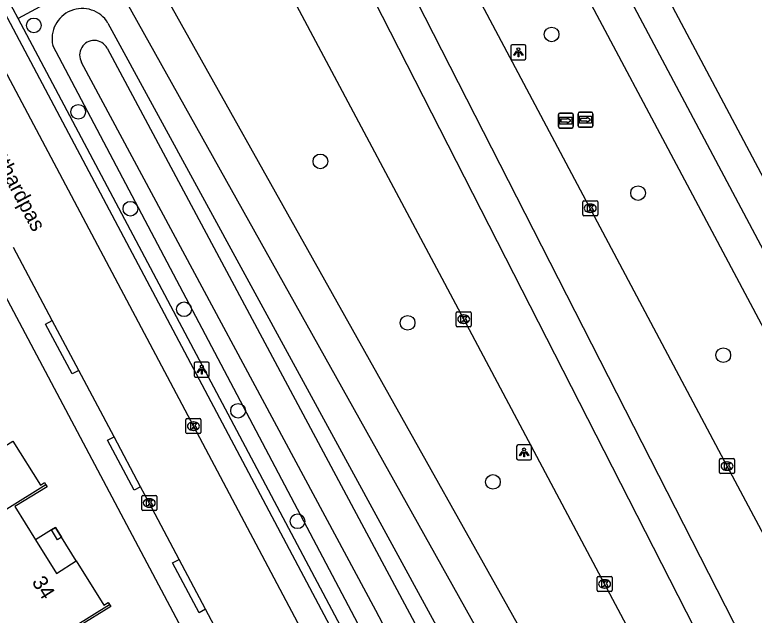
# Model space of a CAD drawing. Extents: x 158838 to 160074, y 386376 to 387776.
# Drawn here: x 159225.91 to 159275.17, y 387072.03 to 387112.04 of the extents above; entities that cross this region are included whole.
import ezdxf

# ---------------------------------------------------------------- set-up
doc = ezdxf.new("R2010")
doc.units = 0
for name, color, linetype in [('IMGEO_Berm_groen', 7, 'Continuous'), ('IMGEO_Boom', 7, 'Continuous'), ('IMGEO_Fietspad_gesloten', 7, 'Continuous'), ('IMGEO_Kolk', 7, 'Continuous'), ('IMGEO_Lichtpunt', 7, 'Continuous'), ('IMGEO_Openbare_ruimte_label', 7, 'Continuous'), ('IMGEO_Pand', 7, 'Continuous'), ('IMGEO_Pand_nummerreeks', 7, 'Continuous'), ('IMGEO_Pand_overbouw', 7, 'Continuous'), ('IMGEO_Rijbaan_lokaal_gesloten', 7, 'Continuous'), ('IMGEO_Rijbaan_lokaal_open', 7, 'Continuous'), ('IMGEO_Voetpad_open', 7, 'Continuous'), ('IMGEO_Waterloop', 7, 'Continuous'), ('IMGEO_Wegwijzer', 7, 'Continuous')]:
    doc.layers.add(name, color=color, linetype=linetype)

msp = doc.modelspace()

# ---------------------------------------------------------------- linework, layer by layer
at = {"layer": 'IMGEO_Berm_groen'}
for points in [[(159232.122, 387111.496), (159272.514, 387037.369)], [(159268.044, 387034.942), (159228.447, 387109.997)]]:
    msp.add_lwpolyline(points, dxfattribs=at)
msp.add_arc((159230.405, 387110.451), 2.01, 31.3221, 193.0582, dxfattribs=at)
at = {"layer": 'IMGEO_Boom'}
for centre in [(159227.183, 387111.339), (159261.673, 387110.732), (159230.14, 387105.578), (159246.274, 387102.278), (159267.435, 387100.161), (159233.613, 387099.119), (159237.187, 387092.418), (159252.081, 387091.516), (159273.111, 387089.363), (159240.785, 387085.656), (159257.766, 387080.919), (159244.747, 387078.294)]:
    msp.add_circle(centre, 0.489, dxfattribs=at)
at = {"layer": 'IMGEO_Fietspad_gesloten'}
for points in [[(159314.185, 387024.122), (159313.935, 387024.592), (159304.248, 387042.785), (159259.512, 387127.003), (159257.832, 387130.098)], [(159256.446, 387127.537), (159257.729, 387125.109), (159294.989, 387055.058)], [(159234.539, 387115.845), (159274.567, 387044.384)], [(159272.288, 387043.244), (159232.161, 387115.069)]]:
    msp.add_lwpolyline(points, dxfattribs=at)
at = {"layer": 'IMGEO_Kolk'}
for p, q in [((159263.745, 387098.725), (159263.745, 387099.577)), ((159263.82, 387099.651), (159264.672, 387099.651)), ((159264.746, 387099.577), (159264.746, 387098.725)), ((159264.233, 387099.431), (159264.258, 387099.431)), ((159264.672, 387098.651), (159263.82, 387098.651)), ((159264.256, 387098.871), (159264.231, 387098.871)), ((159255.318, 387091.334), (159255.318, 387092.186)), ((159255.393, 387092.26), (159256.245, 387092.26)), ((159256.319, 387092.186), (159256.319, 387091.334)), ((159255.806, 387092.04), (159255.831, 387092.04)), ((159256.245, 387091.26), (159255.393, 387091.26)), ((159255.829, 387091.48), (159255.804, 387091.48)), ((159237.315, 387084.207), (159237.315, 387085.059)), ((159237.39, 387085.133), (159238.242, 387085.133)), ((159237.803, 387084.913), (159237.828, 387084.913)), ((159238.316, 387085.059), (159238.316, 387084.207)), ((159237.826, 387084.353), (159237.801, 387084.353)), ((159238.242, 387084.133), (159237.39, 387084.133)), ((159272.862, 387081.547), (159272.862, 387082.399)), ((159272.937, 387082.473), (159273.789, 387082.473)), ((159273.35, 387082.253), (159273.375, 387082.253)), ((159273.863, 387082.399), (159273.863, 387081.547)), ((159273.789, 387081.473), (159272.937, 387081.473)), ((159273.373, 387081.693), (159273.348, 387081.693)), ((159234.374, 387079.086), (159234.374, 387079.938)), ((159234.449, 387080.012), (159235.301, 387080.012)), ((159234.862, 387079.792), (159234.887, 387079.792)), ((159235.375, 387079.938), (159235.375, 387079.086)), ((159235.301, 387079.012), (159234.449, 387079.012)), ((159234.885, 387079.232), (159234.86, 387079.232)), ((159264.707, 387073.693), (159264.707, 387074.545)), ((159264.782, 387074.619), (159265.634, 387074.619)), ((159265.195, 387074.399), (159265.22, 387074.399)), ((159265.708, 387074.545), (159265.708, 387073.693)), ((159265.634, 387073.619), (159264.782, 387073.619)), ((159265.218, 387073.839), (159265.193, 387073.839))]:
    msp.add_line(p, q, dxfattribs=at)
for points in [[(159263.745, 387098.725), (159263.745, 387099.577)], [(159263.82, 387099.651), (159264.672, 387099.651)], [(159264.746, 387099.577), (159264.746, 387098.725)], [(159264.066, 387099.351), (159264.189, 387099.351), (159264.189, 387099.2), (159264.319, 387099.351), (159264.483, 387099.351), (159264.337, 387099.2), (159264.49, 387098.951), (159264.338, 387098.951), (159264.253, 387099.115), (159264.189, 387099.048), (159264.189, 387098.951), (159264.066, 387098.951), (159264.066, 387099.351)], [(159264.672, 387098.651), (159263.82, 387098.651)], [(159255.318, 387091.334), (159255.318, 387092.186)], [(159255.393, 387092.26), (159256.245, 387092.26)], [(159256.319, 387092.186), (159256.319, 387091.334)], [(159255.639, 387091.96), (159255.762, 387091.96), (159255.762, 387091.809), (159255.892, 387091.96), (159256.056, 387091.96), (159255.91, 387091.809), (159256.063, 387091.56), (159255.911, 387091.56), (159255.826, 387091.724), (159255.762, 387091.657), (159255.762, 387091.56), (159255.639, 387091.56), (159255.639, 387091.96)], [(159256.245, 387091.26), (159255.393, 387091.26)], [(159237.315, 387084.207), (159237.315, 387085.059)], [(159237.39, 387085.133), (159238.242, 387085.133)], [(159237.636, 387084.833), (159237.759, 387084.833), (159237.759, 387084.682), (159237.889, 387084.833), (159238.053, 387084.833), (159237.907, 387084.682), (159238.06, 387084.433), (159237.908, 387084.433), (159237.823, 387084.597), (159237.759, 387084.53), (159237.759, 387084.433), (159237.636, 387084.433), (159237.636, 387084.833)], [(159238.316, 387085.059), (159238.316, 387084.207)], [(159238.242, 387084.133), (159237.39, 387084.133)], [(159272.862, 387081.547), (159272.862, 387082.399)], [(159272.937, 387082.473), (159273.789, 387082.473)], [(159273.863, 387082.399), (159273.863, 387081.547)], [(159273.183, 387082.173), (159273.306, 387082.173), (159273.306, 387082.022), (159273.436, 387082.173), (159273.6, 387082.173), (159273.454, 387082.022), (159273.607, 387081.773), (159273.455, 387081.773), (159273.37, 387081.937), (159273.306, 387081.87), (159273.306, 387081.773), (159273.183, 387081.773), (159273.183, 387082.173)], [(159273.789, 387081.473), (159272.937, 387081.473)], [(159234.374, 387079.086), (159234.374, 387079.938)], [(159234.449, 387080.012), (159235.301, 387080.012)], [(159235.375, 387079.938), (159235.375, 387079.086)], [(159234.695, 387079.712), (159234.818, 387079.712), (159234.818, 387079.561), (159234.948, 387079.712), (159235.112, 387079.712), (159234.966, 387079.561), (159235.119, 387079.312), (159234.967, 387079.312), (159234.882, 387079.476), (159234.818, 387079.409), (159234.818, 387079.312), (159234.695, 387079.312), (159234.695, 387079.712)], [(159235.301, 387079.012), (159234.449, 387079.012)], [(159264.707, 387073.693), (159264.707, 387074.545)], [(159264.782, 387074.619), (159265.634, 387074.619)], [(159265.708, 387074.545), (159265.708, 387073.693)], [(159265.028, 387074.319), (159265.151, 387074.319), (159265.151, 387074.168), (159265.281, 387074.319), (159265.445, 387074.319), (159265.299, 387074.168), (159265.452, 387073.919), (159265.3, 387073.919), (159265.215, 387074.083), (159265.151, 387074.016), (159265.151, 387073.919), (159265.028, 387073.919), (159265.028, 387074.319)], [(159265.634, 387073.619), (159264.782, 387073.619)]]:
    msp.add_lwpolyline(points, dxfattribs=at)
for centre, start, end in [((159263.822, 387099.575), 91.552, 178.448), ((159263.822, 387099.575), 91.552, 178.448), ((159264.67, 387099.575), 1.552, 88.448), ((159264.67, 387099.575), 1.552, 88.448), ((159263.822, 387098.727), 181.552, 268.448), ((159263.822, 387098.727), 181.552, 268.448), ((159264.67, 387098.727), 271.552, 358.448), ((159264.67, 387098.727), 271.552, 358.448), ((159255.395, 387092.184), 91.552, 178.448), ((159255.395, 387092.184), 91.552, 178.448), ((159256.243, 387092.184), 1.552, 88.448), ((159256.243, 387092.184), 1.552, 88.448), ((159255.395, 387091.336), 181.552, 268.448), ((159255.395, 387091.336), 181.552, 268.448), ((159256.243, 387091.336), 271.552, 358.448), ((159256.243, 387091.336), 271.552, 358.448), ((159237.392, 387085.057), 91.552, 178.448), ((159237.392, 387085.057), 91.552, 178.448), ((159238.24, 387085.057), 1.552, 88.448), ((159238.24, 387085.057), 1.552, 88.448), ((159237.392, 387084.209), 181.552, 268.448), ((159237.392, 387084.209), 181.552, 268.448), ((159238.24, 387084.209), 271.552, 358.448), ((159238.24, 387084.209), 271.552, 358.448), ((159272.939, 387082.397), 91.552, 178.448), ((159272.939, 387082.397), 91.552, 178.448), ((159273.787, 387082.397), 1.552, 88.448), ((159273.787, 387082.397), 1.552, 88.448), ((159272.939, 387081.549), 181.552, 268.448), ((159272.939, 387081.549), 181.552, 268.448), ((159273.787, 387081.549), 271.552, 358.448), ((159273.787, 387081.549), 271.552, 358.448), ((159234.451, 387079.936), 91.552, 178.448), ((159234.451, 387079.936), 91.552, 178.448), ((159235.299, 387079.936), 1.552, 88.448), ((159235.299, 387079.936), 1.552, 88.448), ((159234.451, 387079.088), 181.552, 268.448), ((159234.451, 387079.088), 181.552, 268.448), ((159235.299, 387079.088), 271.552, 358.448), ((159235.299, 387079.088), 271.552, 358.448), ((159264.784, 387074.543), 91.552, 178.448), ((159264.784, 387074.543), 91.552, 178.448), ((159265.632, 387074.543), 1.552, 88.448), ((159265.632, 387074.543), 1.552, 88.448), ((159264.784, 387073.695), 181.552, 268.448), ((159264.784, 387073.695), 181.552, 268.448), ((159265.632, 387073.695), 271.552, 358.448), ((159265.632, 387073.695), 271.552, 358.448)]:
    msp.add_arc(centre, 0.0765, start, end, dxfattribs=at)
for centre, major_axis, ratio, start_param, end_param in [((159264.232, 387099.151), (-0.387, 0.002), 0.722429, 4.712389, 7.853982), ((159264.257, 387099.151), (-0.39, 0.002), 0.717154, 1.570796, 4.712389), ((159255.805, 387091.76), (-0.387, 0.002), 0.722429, 4.712389, 7.853982), ((159255.83, 387091.76), (-0.39, 0.002), 0.717154, 1.570796, 4.712389), ((159237.802, 387084.633), (-0.387, 0.002), 0.722429, 4.712389, 7.853982), ((159237.827, 387084.633), (-0.39, 0.002), 0.717154, 1.570796, 4.712389), ((159273.349, 387081.973), (-0.387, 0.002), 0.722429, 4.712389, 7.853982), ((159273.374, 387081.973), (-0.39, 0.002), 0.717154, 1.570796, 4.712389), ((159234.861, 387079.512), (-0.387, 0.002), 0.722429, 4.712389, 7.853982), ((159234.886, 387079.512), (-0.39, 0.002), 0.717154, 1.570796, 4.712389), ((159265.194, 387074.119), (-0.387, 0.002), 0.722429, 4.712389, 7.853982), ((159265.219, 387074.119), (-0.39, 0.002), 0.717154, 1.570796, 4.712389)]:
    msp.add_ellipse(centre, major_axis=major_axis, ratio=ratio, start_param=start_param, end_param=end_param, dxfattribs=at)
at = {"layer": 'IMGEO_Lichtpunt'}
for p, q in [((159258.965, 387109.952), (159258.965, 387109.145)), ((159258.965, 387109.952), (159258.965, 387109.145)), ((159259.867, 387110.047), (159259.059, 387110.047)), ((159259.867, 387110.047), (159259.059, 387110.047)), ((159259.961, 387109.145), (159259.961, 387109.952)), ((159259.961, 387109.145), (159259.961, 387109.952)), ((159259.059, 387109.051), (159259.867, 387109.051)), ((159259.059, 387109.051), (159259.867, 387109.051)), ((159237.87, 387088.804), (159237.87, 387087.997)), ((159237.87, 387088.804), (159237.87, 387087.997)), ((159238.772, 387088.899), (159237.964, 387088.899)), ((159238.772, 387088.899), (159237.964, 387088.899)), ((159238.866, 387087.997), (159238.866, 387088.804)), ((159238.866, 387087.997), (159238.866, 387088.804)), ((159237.964, 387087.903), (159238.772, 387087.903)), ((159237.964, 387087.903), (159238.772, 387087.903)), ((159259.347, 387083.286), (159259.347, 387082.479)), ((159259.347, 387083.286), (159259.347, 387082.479)), ((159260.249, 387083.381), (159259.441, 387083.381)), ((159260.249, 387083.381), (159259.441, 387083.381)), ((159260.343, 387082.479), (159260.343, 387083.286)), ((159260.343, 387082.479), (159260.343, 387083.286)), ((159259.441, 387082.385), (159260.249, 387082.385)), ((159259.441, 387082.385), (159260.249, 387082.385))]:
    msp.add_line(p, q, dxfattribs=at)
for points in [[(159259.339, 387109.616), (159259.378, 387109.588), (159259.19, 387109.326), (159259.152, 387109.353), (159259.339, 387109.616)], [(159259.441, 387109.568), (159259.488, 387109.568), (159259.488, 387109.246), (159259.441, 387109.246), (159259.441, 387109.568)], [(159259.551, 387109.588), (159259.589, 387109.615), (159259.776, 387109.353), (159259.737, 387109.325), (159259.551, 387109.588)], [(159238.244, 387088.468), (159238.283, 387088.44), (159238.095, 387088.178), (159238.057, 387088.205), (159238.244, 387088.468)], [(159238.346, 387088.42), (159238.393, 387088.42), (159238.393, 387088.098), (159238.346, 387088.098), (159238.346, 387088.42)], [(159238.456, 387088.44), (159238.494, 387088.467), (159238.681, 387088.205), (159238.642, 387088.177), (159238.456, 387088.44)], [(159259.721, 387082.95), (159259.76, 387082.922), (159259.572, 387082.66), (159259.534, 387082.687), (159259.721, 387082.95)], [(159259.823, 387082.902), (159259.87, 387082.902), (159259.87, 387082.58), (159259.823, 387082.58), (159259.823, 387082.902)], [(159259.933, 387082.922), (159259.971, 387082.949), (159260.158, 387082.687), (159260.119, 387082.659), (159259.933, 387082.922)]]:
    msp.add_lwpolyline(points, dxfattribs=at)
for centre in [(159259.464, 387109.75), (159238.369, 387088.602), (159259.846, 387083.084)]:
    msp.add_circle(centre, 0.0994, dxfattribs=at)
for centre, start, end in [((159259.059, 387109.952), 90, 180), ((159259.059, 387109.952), 90, 180), ((159259.867, 387109.952), 0, 90), ((159259.867, 387109.952), 0, 90), ((159259.059, 387109.145), 180, 270), ((159259.059, 387109.145), 180, 270), ((159259.867, 387109.145), 270, 0), ((159259.867, 387109.145), 270, 360), ((159237.964, 387088.804), 90, 180), ((159237.964, 387088.804), 90, 180), ((159238.772, 387088.804), 0, 90), ((159238.772, 387088.804), 0, 90), ((159237.964, 387087.997), 180, 270), ((159237.964, 387087.997), 180, 270), ((159238.772, 387087.997), 270, 0), ((159238.772, 387087.997), 270, 360), ((159259.441, 387083.286), 90, 180), ((159259.441, 387083.286), 90, 180), ((159260.249, 387083.286), 0, 90), ((159260.249, 387083.286), 0, 90), ((159259.441, 387082.479), 180, 270), ((159259.441, 387082.479), 180, 270), ((159260.249, 387082.479), 270, 0), ((159260.249, 387082.479), 270, 360)]:
    msp.add_arc(centre, 0.0946, start, end, dxfattribs=at)
at = {"layer": 'IMGEO_Pand'}
for points in [[(159223.75, 387088.709), (159223.834, 387088.574), (159221.679, 387087.231), (159223.057, 387085.03), (159224.463, 387082.802), (159225.784, 387083.627), (159227.624, 387080.693), (159227.904, 387080.868), (159227.989, 387080.733)], [(159227.989, 387080.733), (159217.564, 387074.229)], [(159227.989, 387080.733), (159228.074, 387080.597), (159225.925, 387079.268), (159227.285, 387077.052), (159228.691, 387074.825), (159230.012, 387075.65), (159231.852, 387072.71), (159232.132, 387072.886), (159232.217, 387072.75)], [(159228.616, 387077.879), (159229.025, 387077.226), (159228.762, 387077.062), (159228.352, 387077.716), (159228.616, 387077.879)], [(159221.79, 387066.257), (159232.217, 387072.75)], [(159232.217, 387072.75), (159232.302, 387072.614), (159230.151, 387071.292), (159231.509, 387069.082), (159232.92, 387066.848), (159234.24, 387067.673), (159236.08, 387064.736), (159236.361, 387064.912), (159236.446, 387064.776)]]:
    msp.add_lwpolyline(points, dxfattribs=at)
at = {"layer": 'IMGEO_Pand_overbouw'}
msp.add_lwpolyline([(159229.025, 387077.226), (159228.616, 387077.879), (159228.352, 387077.716), (159227.285, 387077.052), (159228.691, 387074.825), (159230.012, 387075.65)], close=True, dxfattribs=at)
at = {"layer": 'IMGEO_Rijbaan_lokaal_gesloten'}
for points in [[(159289.372, 387051.973), (159282.971, 387063.93), (159280.972, 387067.73), (159273.362, 387081.973), (159253.253, 387119.862), (159251.577, 387122.927), (159250.755, 387124.426)], [(159247.673, 387122.786), (159284.887, 387049.796), (159284.892, 387049.786)], [(159282.694, 387048.649), (159245.482, 387121.606)], [(159279.646, 387046.923), (159274.342, 387056.94), (159265.209, 387074.119), (159255.82, 387091.76), (159244.354, 387113.334), (159241.175, 387119.339)]]:
    msp.add_lwpolyline(points, dxfattribs=at)
at = {"layer": 'IMGEO_Rijbaan_lokaal_open'}
for points in [[(159185.962, 387182.529), (159186.994, 387180.354), (159195.093, 387165.124), (159206.383, 387143.913), (159215.465, 387126.768), (159216.713, 387124.427), (159225.399, 387108.034), (159237.811, 387084.633), (159248.115, 387065.172), (159257.979, 387046.591), (159267.363, 387028.878), (159268.082, 387027.672)], [(159228.412, 387091.668), (159225.827, 387096.54)], [(159230.181, 387088.351), (159228.412, 387091.668)], [(159232.537, 387083.923), (159230.181, 387088.351)], [(159234.3, 387080.597), (159232.537, 387083.923)], [(159236.866, 387075.757), (159234.872, 387079.512), (159234.3, 387080.597)], [(159238.628, 387072.438), (159236.866, 387075.757)], [(159240.974, 387068.001), (159238.628, 387072.438)]]:
    msp.add_lwpolyline(points, dxfattribs=at)
at = {"layer": 'IMGEO_Voetpad_open'}
for points in [[(159188.607, 387181.119), (159217.085, 387127.542), (159268.384, 387030.839), (159268.404, 387030.804), (159268.439, 387030.73), (159268.468, 387030.653), (159268.49, 387030.574), (159268.504, 387030.493), (159268.512, 387030.411), (159268.512, 387030.329), (159268.504, 387030.247), (159268.49, 387030.166), (159268.468, 387030.087), (159268.089, 387028.603), (159268.053, 387028.439), (159268.033, 387028.272), (159268.027, 387028.103), (159268.036, 387027.936), (159268.061, 387027.769), (159268.082, 387027.672)], [(159261.184, 387025.643), (159192.812, 387154.528), (159184.858, 387169.495), (159180.565, 387177.574), (159180.465, 387177.724), (159180.352, 387177.865), (159180.227, 387177.995), (159180.091, 387178.113), (159179.944, 387178.219), (159179.789, 387178.311), (159179.627, 387178.389), (159179.458, 387178.452), (159179.284, 387178.5), (159179.106, 387178.532), (159178.926, 387178.548), (159178.746, 387178.548), (159178.566, 387178.532), (159178.388, 387178.5), (159178.214, 387178.452), (159178.045, 387178.389), (159177.883, 387178.311)], [(159343.9, 386973.093), (159329.563, 387000), (159317.744, 387022.183), (159315.894, 387025.664), (159305.108, 387045.958), (159287.565, 387078.987), (159274.488, 387103.639), (159264.081, 387123.241), (159260.709, 387129.351), (159258.414, 387133.568), (159258.621, 387134.669)], [(159232.161, 387115.069), (159226.137, 387111.804)], [(159226.137, 387111.804), (159225.151, 387113.68)], [(159270.438, 387028.309), (159226.137, 387111.804)], [(159230.181, 387088.351), (159229.74, 387088.116), (159227.971, 387091.433), (159228.412, 387091.668)], [(159234.3, 387080.597), (159233.859, 387080.363), (159232.096, 387083.689), (159232.537, 387083.923)], [(159238.628, 387072.438), (159238.187, 387072.204), (159236.424, 387075.523), (159236.866, 387075.757)]]:
    msp.add_lwpolyline(points, dxfattribs=at)
at = {"layer": 'IMGEO_Waterloop'}
msp.add_lwpolyline([(159232.07, 387109.817), (159271.865, 387035.443), (159269.914, 387034.437), (159263.508, 387046.573), (159249.976, 387072.343), (159230.366, 387108.873)], dxfattribs=at)
msp.add_arc((159231.21, 387109.359), 0.974, 28.0682, 209.9039, dxfattribs=at)
at = {"layer": 'IMGEO_Wegwijzer'}
for p, q in [((159262.131, 387104.597), (159262.131, 387105.397)), ((159262.131, 387105.397), (159262.131, 387104.597)), ((159262.231, 387105.497), (159263.021, 387105.497)), ((159263.021, 387105.497), (159262.231, 387105.497)), ((159263.121, 387105.397), (159263.121, 387104.597)), ((159263.121, 387104.597), (159263.121, 387105.397)), ((159263.439, 387104.652), (159263.439, 387105.452)), ((159263.439, 387105.452), (159263.439, 387104.652)), ((159263.539, 387105.552), (159264.329, 387105.552)), ((159264.329, 387105.552), (159263.539, 387105.552)), ((159264.429, 387105.452), (159264.429, 387104.652)), ((159264.429, 387104.652), (159264.429, 387105.452)), ((159263.021, 387104.497), (159262.231, 387104.497)), ((159262.231, 387104.497), (159263.021, 387104.497)), ((159264.329, 387104.552), (159263.539, 387104.552)), ((159263.539, 387104.552), (159264.329, 387104.552))]:
    msp.add_line(p, q, dxfattribs=at)
for points in [[(159262.232, 387105.229), (159263.02, 387105.229), (159263.02, 387104.765), (159262.232, 387104.765), (159262.232, 387105.229)], [(159262.297, 387105.081), (159262.297, 387104.997), (159262.297, 387104.913), (159262.708, 387104.913), (159262.708, 387104.83), (159262.955, 387104.997), (159262.708, 387105.164), (159262.708, 387105.081), (159262.297, 387105.081)], [(159263.54, 387105.284), (159264.328, 387105.284), (159264.328, 387104.82), (159263.54, 387104.82), (159263.54, 387105.284)], [(159263.605, 387105.136), (159263.605, 387105.052), (159263.605, 387104.968), (159264.016, 387104.968), (159264.016, 387104.885), (159264.263, 387105.052), (159264.016, 387105.219), (159264.016, 387105.136), (159263.605, 387105.136)]]:
    msp.add_lwpolyline(points, dxfattribs=at)
for centre, start, end in [((159262.231, 387105.397), 90, 180), ((159262.231, 387105.397), 90, 180), ((159263.021, 387105.397), 0, 90), ((159263.021, 387105.397), 360, 90), ((159263.539, 387105.452), 90, 180), ((159263.539, 387105.452), 90, 180), ((159264.329, 387105.452), 0, 90), ((159264.329, 387105.452), 360, 90), ((159262.231, 387104.597), 180, 270), ((159262.231, 387104.597), 180, 270), ((159263.021, 387104.597), 270, 0), ((159263.021, 387104.597), 270, 0), ((159263.539, 387104.652), 180, 270), ((159263.539, 387104.652), 180, 270), ((159264.329, 387104.652), 270, 0), ((159264.329, 387104.652), 270, 0)]:
    msp.add_arc(centre, 0.1, start, end, dxfattribs=at)

# ---------------------------------------------------------------- texts
at = {"layer": 'IMGEO_Openbare_ruimte_label'}
msp.add_text('Gotthardpas', height=1, rotation=297.8973, dxfattribs=at).set_placement((159223.691, 387104.019))
at = {"layer": 'IMGEO_Pand_nummerreeks'}
msp.add_text('34', height=1, rotation=302.051, dxfattribs=at).set_placement((159227.016, 387074.255))

doc.saveas('drawing.dxf')
